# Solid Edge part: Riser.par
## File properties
Author: davee
Template: Normal.par
Last saved by: davee
Revision: 8
Application: Solid Edge
Accuracy: 0.990
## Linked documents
MH Die Plate.par
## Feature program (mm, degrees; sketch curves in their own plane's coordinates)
sketch for "ExtrudedProtrusion_1" plane through (0, 0, -36.2) normal (0, 0, -1) x-axis (-1, 0, 0)
  line (-100, -100) -> (-63, -100)
  line (-63, -100) -> (-63, 100)
  line (-63, 100) -> (-100, 100)
  line (-100, 100) -> (-100, -100)
extrude "ExtrudedProtrusion_1" add finite 80 along +normal
sketch for "Hole_1" plane through (81.5, 0, -116.2) normal (0, 0, -1) x-axis (0, -1, 0)
  line (0, 0) -> (0, 0)
  hole centre (-49, 1.5) bore radius 6.25
hole "Hole_1" diameter 12.5 through
sketch for "unnamed Hole 1" plane through (81.5, 0, -116.2) normal (0, 0, -1) x-axis (0, -1, 0)
  hole centre (49, 1.5) bore radius 6.25
hole "unnamed Hole 1" through
pattern "unnamed Pattern 1" of "Hole_1", "unnamed Hole 1"
Other named dimensions: "CopyConstruction_1": YScale = 1; ZScale = 1
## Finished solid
Body 1: solid body, 8 faces, 16 edges, 8 vertices.
  Faces by surface: plane 6, cylinder 2
  Edges by curve: line 12, circle 4
Body 2: solid body, 224 faces, 506 edges, 282 vertices.
  Faces by surface: plane 99, cylinder 67, torus 20, cone 18, spline 6, swept 6, sphere 4, spun 4
  Edges by curve: line 289, circle 150, intersection 21, curve on surface 18, spline 18, ellipse 10
Bounding box of the edges (mm; curved faces can reach further): 200.000 x 200.000 x 118.230, from (-100, -100, -116.2) to (100, 100, 2.03).
Cylindrical faces by radius (mm): R0.7575 x6, R0.808 x8, R1.01 x9, R1.515 x2, R2.03 x14, R3 x1, R3.03 x3, R3.045 x2, R5 x6, R5.053 x4, R6.25 x2, R7 x1, R10 x1, R10.15 x1, R13.5 x4, R16 x4, R25.8825 x1
Conical faces (half-angle, radius in mm at the cone's reference point): 1 deg R1.7675 x2, 1 deg R2.424 x2, 3 deg R1.515 x8, 3 deg R3.8099 x1, 3 deg R3.8205 x1, 59 deg R5.053 x4
Toroidal faces (ring radius, tube radius in mm): R0.505 r1.01 x2, R0.7575 r0.7575 x2, R2.02 r1.01 x2, R2.2725 r0.7575 x2, R2.2818 r0.808 x8, R3.0431 r0.808 x1, R3.0538 r0.808 x1, R5.43 r1.01 x1, R5.4406 r1.01 x1
Spherical faces by radius (mm): R2.03 x4
Planar faces by outward normal: +x 14, +y 12, +z 29, -x 13, -y 12, -z 7, oblique 18
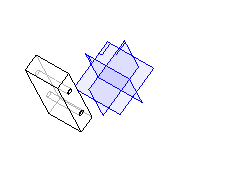
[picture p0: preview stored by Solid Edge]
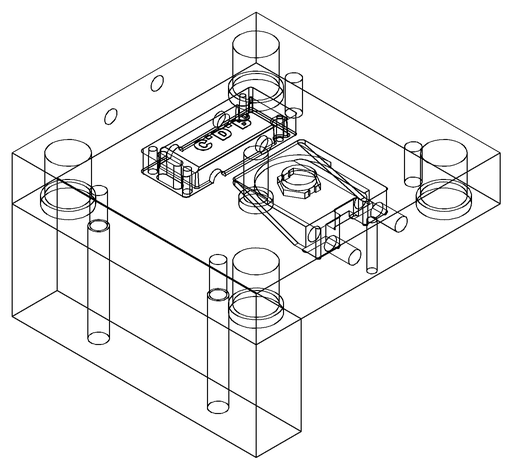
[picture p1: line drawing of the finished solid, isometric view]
